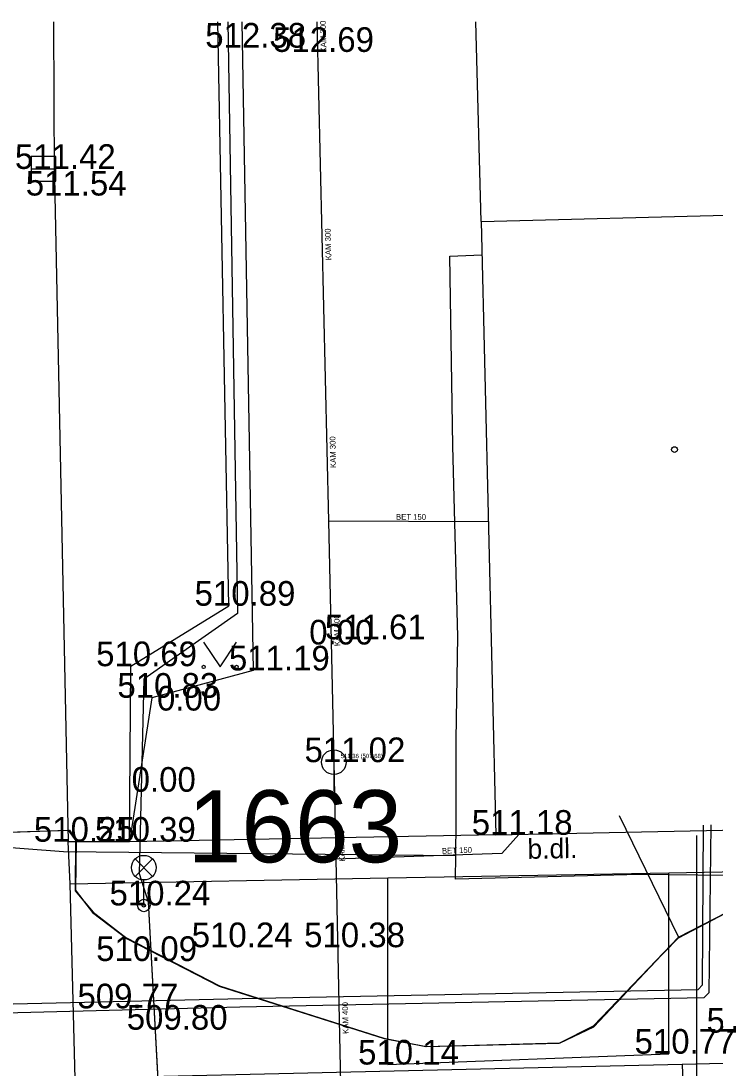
# Model space of a CAD drawing. Extents: x -669642 to -669119, y -1131006 to -1130466.
# Drawn here: x -669468.22 to -669447.11, y -1130529.04 to -1130497.18 of the extents above; entities that cross this region are included whole.
import ezdxf

# ---------------------------------------------------------------- set-up
doc = ezdxf.new("R2010")
doc.units = 0
for name, color, linetype in [('G_Bod_tecka', 7, 'Continuous'), ('G_Bod_vyska', 7, 'Continuous'), ('G_Breh_Teren', 7, 'Continuous'), ('G_Budovy-znacky', 7, 'Continuous'), ('G_Budovy_Objekty', 7, 'Continuous'), ('G_Cesty_Schody', 7, 'Continuous'), ('G_Objekty_technicke', 7, 'Continuous'), ('G_Plochy_zpevnene', 7, 'Continuous'), ('G_Popisy_povrchu', 7, 'Continuous'), ('G_Site-kanalizace', 7, 'Continuous'), ('G_Z_CHRANICKA-TEPLOVOD_kotovane', 7, 'Continuous'), ('G_Z_CHRANICKA-TEPLOVOD_zahozene', 7, 'Continuous'), ('G_Z_ELsilove_podz_kotovane', 7, 'Continuous'), ('G_Z_KANAL_podz_kotovane', 7, 'Continuous'), ('G_Z_PLYNY_podz_geodeticky', 7, 'Continuous'), ('G_Z_SPOJE_podz_geodeticky', 7, 'Continuous'), ('G_Z_SPOJE_podz_kotovane', 7, 'Continuous'), ('G_Z_SPOJE_podz_priblizne', 7, 'Continuous'), ('G_Z_SPOJE_podz_zahozene', 7, 'Continuous'), ('G_Zelen-okraj', 7, 'Continuous'), ('G_Zelen-Znacky', 7, 'Continuous'), ('Vrstva 1', 7, 'Continuous'), ('Vrstva 10', 7, 'Continuous'), ('Vrstva 11', 7, 'Continuous'), ('Vrstva 13', 7, 'Continuous'), ('Vrstva 17', 7, 'Continuous'), ('Vrstva 2', 7, 'Continuous'), ('Vrstva 3', 7, 'Continuous'), ('Vrstva 4', 7, 'Continuous'), ('Vrstva 8', 7, 'Continuous')]:
    doc.layers.add(name, color=color, linetype=linetype)

msp = doc.modelspace()

# ---------------------------------------------------------------- linework, layer by layer
at = {"layer": 'G_Bod_tecka'}
for p, q in [((-669461.59, -1130497.99), (-669461.59, -1130497.99)), ((-669459.51, -1130498.12), (-669459.51, -1130498.12)), ((-669467.53, -1130501.68), (-669467.53, -1130501.68)), ((-669467.19, -1130502.49), (-669467.19, -1130502.49)), ((-669461.89, -1130514.97), (-669461.89, -1130514.97)), ((-669458.14, -1130515.99), (-669458.14, -1130515.99)), ((-669458.67, -1130516.15), (-669458.67, -1130516.15)), ((-669464.87, -1130516.81), (-669464.87, -1130516.81)), ((-669461.15, -1130516.94), (-669461.15, -1130516.94)), ((-669464.24, -1130517.77), (-669464.24, -1130517.77)), ((-669463.3, -1130518.16), (-669463.3, -1130518.16)), ((-669458.7, -1130519.73), (-669458.7, -1130519.73)), ((-669464.07, -1130520.63), (-669464.07, -1130520.63)), ((-669453.77, -1130521.94), (-669453.77, -1130521.94)), ((-669466.78, -1130522.15), (-669466.78, -1130522.15)), ((-669464.92, -1130522.15), (-669464.92, -1130522.15)), ((-669464.48, -1130524.09), (-669464.48, -1130524.09)), ((-669461.98, -1130525.36), (-669461.98, -1130525.36)), ((-669458.56, -1130525.36), (-669458.56, -1130525.36)), ((-669464.86, -1130525.78), (-669464.86, -1130525.78)), ((-669465.31, -1130527.22), (-669465.31, -1130527.22)), ((-669463.79, -1130527.87), (-669463.79, -1130527.87)), ((-669448.51, -1130528.6), (-669448.51, -1130528.6)), ((-669457.06, -1130528.93), (-669457.06, -1130528.93))]:
    msp.add_line(p, q, dxfattribs=at)
at = {"layer": 'G_Breh_Teren'}
for p, q in [((-669461.502, -1130497.207), (-669461.15, -1130516.94)), ((-669461.15, -1130516.94), (-669464.24, -1130517.77)), ((-669464.24, -1130517.77), (-669464.92, -1130522.15))]:
    msp.add_line(p, q, dxfattribs=at)
at = {"layer": 'G_Budovy-znacky'}
msp.add_circle((-669448.34, -1130510.22), 0.0875, dxfattribs=at)
at = {"layer": 'G_Budovy_Objekty'}
for p, q in [((-669454.22, -1130503.28), (-669454.384, -1130497.207)), ((-669454.22, -1130503.28), (-669442.81, -1130502.99)), ((-669454.22, -1130503.28), (-669453.77, -1130521.94)), ((-669453.77, -1130521.94), (-669442.37, -1130521.7))]:
    msp.add_line(p, q, dxfattribs=at)
at = {"layer": 'G_Cesty_Schody'}
for p, q in [((-669467.2, -1130501.87), (-669467.215, -1130497.207)), ((-669467.2, -1130501.87), (-669467.19, -1130502.49)), ((-669467.19, -1130502.49), (-669466.78, -1130522.15))]:
    msp.add_line(p, q, dxfattribs=at)
at = {"layer": 'G_Objekty_technicke'}
for p, q in [((-669464.745, -1130522.675), (-669464.215, -1130523.205)), ((-669464.745, -1130523.205), (-669464.215, -1130522.675)), ((-669464.48, -1130524.09), (-669464.48, -1130523.315))]:
    msp.add_line(p, q, dxfattribs=at)
for centre, radius in [((-669464.48, -1130522.94), 0.375), ((-669464.48, -1130524.09), 0.19), ((-669464.48, -1130524.09), 0.05)]:
    msp.add_circle(centre, radius, dxfattribs=at)
at = {"layer": 'G_Plochy_zpevnene'}
for p, q in [((-669461.89, -1130514.97), (-669462.226, -1130497.207)), ((-669464.87, -1130516.81), (-669461.89, -1130514.97)), ((-669464.92, -1130522.15), (-669464.87, -1130516.81)), ((-669453.77, -1130521.94), (-669464.92, -1130522.15)), ((-669466.72, -1130523.43), (-669466.78, -1130522.15)), ((-669464.92, -1130522.15), (-669466.78, -1130522.15)), ((-669466.52, -1130531.1), (-669466.72, -1130523.43))]:
    msp.add_line(p, q, dxfattribs=at)
msp.add_lwpolyline([(-669466.72, -1130523.43), (-669457.06, -1130523.25), (-669448.51, -1130523.1), (-669439.35, -1130522.93)], dxfattribs=at)
at = {"layer": 'G_Site-kanalizace'}
for p, q in [((-669467.905, -1130501.68), (-669467.155, -1130501.68)), ((-669458.7, -1130519.355), (-669458.7, -1130520.605))]:
    msp.add_line(p, q, dxfattribs=at)
msp.add_lwpolyline([(-669467.905, -1130502.054), (-669467.155, -1130502.054), (-669467.155, -1130501.304), (-669467.905, -1130501.304)], close=True, dxfattribs=at)
msp.add_circle((-669458.7, -1130519.73), 0.375, dxfattribs=at)
at = {"layer": 'G_Z_CHRANICKA-TEPLOVOD_kotovane'}
for points in [[(-669447.23, -1130521.64), (-669447.29, -1130526.75), (-669447.45, -1130526.9), (-669461.56, -1130527.18), (-669481.44, -1130527.69)], [(-669481.1, -1130527.38), (-669461.49, -1130526.92), (-669447.62, -1130526.65), (-669447.49, -1130526.51), (-669447.46, -1130521.65)]]:
    msp.add_lwpolyline(points, dxfattribs=at)
at = {"layer": 'G_Z_CHRANICKA-TEPLOVOD_zahozene'}
msp.add_line((-669447.67, -1130521.96), (-669447.67, -1130535.89), dxfattribs=at)
at = {"layer": 'G_Z_ELsilove_podz_kotovane'}
msp.add_lwpolyline([(-669461.927, -1130497.207), (-669461.63, -1130515.21), (-669464.48, -1130517.2), (-669464.62, -1130523.12), (-669464.35, -1130523.98), (-669463.69, -1130536.15), (-669459.59, -1130539.64), (-669453.93, -1130539.67), (-669453.33, -1130540.17)], dxfattribs=at)
at = {"layer": 'G_Z_KANAL_podz_kotovane'}
msp.add_line((-669454, -1130512.42), (-669458.86, -1130512.4), dxfattribs=at)
for points in [[(-669459.215, -1130497.207), (-669458.86, -1130512.4), (-669458.7, -1130519.73)], [(-669458.7, -1130519.73), (-669458.64, -1130522.68), (-669458.02, -1130552.46)], [(-669453.07, -1130521.93), (-669453.59, -1130522.51), (-669458.64, -1130522.68)]]:
    msp.add_lwpolyline(points, dxfattribs=at)
at = {"layer": 'G_Z_PLYNY_podz_geodeticky'}
for points in [[(-669532.74, -1130558.83), (-669531.49, -1130552.09), (-669534.06, -1130537.73), (-669534.79, -1130531.23), (-669520.82, -1130530.69), (-669481.4, -1130529.69), (-669448.11, -1130528.92), (-669445.21, -1130528.85), (-669441.37, -1130524.47)], [(-669448.11, -1130528.92), (-669447.27, -1130552.99), (-669447.2, -1130556.63)]]:
    msp.add_lwpolyline(points, dxfattribs=at)
at = {"layer": 'G_Z_SPOJE_podz_geodeticky'}
for points in [[(-669454.99, -1130522.58), (-669454.98, -1130521.55), (-669454.98, -1130519.04), (-669454.93, -1130515.91), (-669455.03, -1130512.06), (-669455.08, -1130510.11), (-669455.17, -1130504.33), (-669454.2, -1130504.29)], [(-669454.99, -1130522.58), (-669466.92, -1130522.46), (-669471.85, -1130522.08), (-669482.12, -1130521.24), (-669486.32, -1130521.33)], [(-669434.59, -1130528.46), (-669435.08, -1130525.45), (-669439.85, -1130525.36), (-669446.76, -1130523.18), (-669449.38, -1130523.15), (-669455, -1130523.29), (-669454.99, -1130522.58)]]:
    msp.add_lwpolyline(points, dxfattribs=at)
at = {"layer": 'G_Z_SPOJE_podz_kotovane'}
for points in [[(-669472.14, -1130521.98), (-669466.74, -1130521.8), (-669466.56, -1130522.08), (-669466.57, -1130523.64), (-669466.02, -1130524.29), (-669465.03, -1130525.06), (-669462.18, -1130526.54), (-669457.19, -1130528.13), (-669455.9, -1130528.38), (-669451.82, -1130528.27), (-669450.79, -1130527.78), (-669448.22, -1130525.05), (-669445.3, -1130523.56), (-669441.55, -1130524.64), (-669439.77, -1130525.54), (-669435.75, -1130525.44), (-669435.54, -1130521.19), (-669435.54, -1130516.75), (-669435.48, -1130505.22), (-669435.71, -1130497.207)], [(-669454.99, -1130522.58), (-669454.98, -1130521.55), (-669454.98, -1130519.04), (-669454.93, -1130515.91), (-669455.03, -1130512.06), (-669455.08, -1130510.11), (-669455.17, -1130504.33), (-669454.2, -1130504.29)], [(-669454.99, -1130522.58), (-669466.92, -1130522.46), (-669471.85, -1130522.08), (-669482.12, -1130521.24), (-669486.32, -1130521.33)], [(-669434.59, -1130528.46), (-669435.08, -1130525.45), (-669439.85, -1130525.36), (-669446.76, -1130523.18), (-669449.38, -1130523.15), (-669455, -1130523.29), (-669454.99, -1130522.58)]]:
    msp.add_lwpolyline(points, dxfattribs=at)
at = {"layer": 'G_Z_SPOJE_podz_priblizne'}
for points in [[(-669454.99, -1130522.58), (-669454.98, -1130521.55), (-669454.98, -1130519.04), (-669454.93, -1130515.91), (-669455.03, -1130512.06), (-669455.08, -1130510.11), (-669455.17, -1130504.33), (-669454.2, -1130504.29)], [(-669454.99, -1130522.58), (-669466.92, -1130522.46), (-669471.85, -1130522.08), (-669482.12, -1130521.24), (-669486.32, -1130521.33)], [(-669450.02, -1130521.35), (-669448.22, -1130525.05)], [(-669434.59, -1130528.46), (-669435.08, -1130525.45), (-669439.85, -1130525.36), (-669446.76, -1130523.18), (-669449.38, -1130523.15), (-669455, -1130523.29), (-669454.99, -1130522.58)]]:
    msp.add_lwpolyline(points, dxfattribs=at)
at = {"layer": 'G_Z_SPOJE_podz_zahozene'}
for p, q in [((-669472.13, -1130521.98), (-669466.78, -1130521.8)), ((-669472.1, -1130521.98), (-669466.79, -1130521.8)), ((-669466.79, -1130521.8), (-669466.78, -1130521.8)), ((-669466.78, -1130521.8), (-669466.74, -1130521.8)), ((-669466.78, -1130521.8), (-669466.56, -1130522.1)), ((-669466.74, -1130521.8), (-669466.56, -1130522.08)), ((-669466.56, -1130522.08), (-669466.56, -1130522.1)), ((-669466.56, -1130522.1), (-669466.57, -1130523.64)), ((-669466.56, -1130522.1), (-669466.54, -1130522.12)), ((-669466.54, -1130522.12), (-669466.56, -1130523.62)), ((-669466.57, -1130523.64), (-669466.31, -1130523.95)), ((-669466.56, -1130523.62), (-669466.31, -1130523.95)), ((-669466.31, -1130523.95), (-669466.02, -1130524.29)), ((-669466.31, -1130523.95), (-669466.04, -1130524.3)), ((-669448.22, -1130525.05), (-669446.09, -1130523.96)), ((-669448.22, -1130525.07), (-669446.09, -1130523.96)), ((-669466.04, -1130524.3), (-669464.99, -1130525.11)), ((-669466.02, -1130524.29), (-669465.03, -1130525.06)), ((-669465.03, -1130525.06), (-669462.18, -1130526.54)), ((-669464.99, -1130525.11), (-669462.19, -1130526.54)), ((-669449.12, -1130526), (-669448.22, -1130525.05)), ((-669449.12, -1130526), (-669448.22, -1130525.07)), ((-669450.8, -1130527.75), (-669449.12, -1130526)), ((-669450.79, -1130527.78), (-669449.12, -1130526)), ((-669462.19, -1130526.54), (-669457.18, -1130528.13)), ((-669462.18, -1130526.54), (-669457.19, -1130528.13)), ((-669451.83, -1130528.27), (-669450.8, -1130527.75)), ((-669451.82, -1130528.27), (-669450.79, -1130527.78)), ((-669457.19, -1130528.13), (-669457.18, -1130528.13)), ((-669457.18, -1130528.13), (-669455.9, -1130528.38)), ((-669457.18, -1130528.13), (-669457.17, -1130528.14)), ((-669457.17, -1130528.14), (-669455.88, -1130528.38)), ((-669455.9, -1130528.38), (-669451.83, -1130528.27)), ((-669455.88, -1130528.38), (-669451.85, -1130528.28)), ((-669451.85, -1130528.28), (-669451.83, -1130528.27)), ((-669451.83, -1130528.27), (-669451.82, -1130528.27))]:
    msp.add_line(p, q, dxfattribs=at)
at = {"layer": 'G_Zelen-okraj'}
for p, q in [((-669457.06, -1130528.93), (-669457.06, -1130523.25)), ((-669448.51, -1130528.6), (-669448.51, -1130523.1)), ((-669457.06, -1130528.93), (-669448.51, -1130528.6))]:
    msp.add_line(p, q, dxfattribs=at)
at = {"layer": 'G_Zelen-Znacky'}
for p, q in [((-669462.66, -1130516.08), (-669462.16, -1130516.83)), ((-669462.16, -1130516.83), (-669461.66, -1130516.08))]:
    msp.add_line(p, q, dxfattribs=at)
for centre in [(-669462.66, -1130516.83), (-669461.66, -1130516.83)]:
    msp.add_circle(centre, 0.05, dxfattribs=at)
at = {"layer": 'Vrstva 1'}
msp.add_line((-669464.35, -1130523.98), (-669464.35, -1130523.98), dxfattribs=at)
at = {"layer": 'Vrstva 10'}
for points in [[(-669459.215, -1130497.207), (-669458.859, -1130512.401), (-669458.7, -1130519.73)], [(-669458.7, -1130519.73), (-669458.642, -1130522.681), (-669458.023, -1130552.455)]]:
    msp.add_lwpolyline(points, dxfattribs=at)
at = {"layer": 'Vrstva 11'}
for points in [[(-669472.14, -1130521.98), (-669466.74, -1130521.8), (-669466.56, -1130522.08), (-669466.57, -1130523.64), (-669466.02, -1130524.29), (-669465.03, -1130525.06), (-669462.18, -1130526.54), (-669457.19, -1130528.13), (-669455.9, -1130528.38), (-669451.82, -1130528.27), (-669450.79, -1130527.78), (-669448.22, -1130525.05), (-669445.3, -1130523.56), (-669441.55, -1130524.64), (-669439.77, -1130525.54), (-669435.75, -1130525.44), (-669435.54, -1130521.19), (-669435.54, -1130516.75), (-669435.48, -1130505.22), (-669435.71, -1130497.207)], [(-669472.101, -1130521.981), (-669466.785, -1130521.8), (-669466.543, -1130522.122), (-669466.563, -1130523.616), (-669466.039, -1130524.302), (-669464.99, -1130525.109), (-669462.187, -1130526.541), (-669457.172, -1130528.135), (-669455.882, -1130528.377), (-669451.848, -1130528.277), (-669450.799, -1130527.752), (-669448.218, -1130525.068), (-669445.304, -1130523.555), (-669441.533, -1130524.645), (-669439.798, -1130525.532), (-669435.745, -1130525.432), (-669435.543, -1130521.235), (-669435.543, -1130516.747), (-669435.482, -1130505.21), (-669435.689, -1130497.207)], [(-669472.101, -1130521.981), (-669466.785, -1130521.8), (-669466.543, -1130522.122), (-669466.563, -1130523.616), (-669466.039, -1130524.302), (-669464.99, -1130525.109), (-669462.187, -1130526.541), (-669457.172, -1130528.135), (-669455.882, -1130528.377), (-669451.848, -1130528.277), (-669450.799, -1130527.752), (-669448.218, -1130525.068), (-669445.304, -1130523.555), (-669441.533, -1130524.645), (-669439.798, -1130525.532), (-669435.745, -1130525.432), (-669435.543, -1130521.235), (-669435.543, -1130516.747), (-669435.482, -1130505.21), (-669435.689, -1130497.207)]]:
    msp.add_lwpolyline(points, dxfattribs=at)
at = {"layer": 'Vrstva 13'}
msp.add_line((-669454, -1130512.417), (-669458.859, -1130512.401), dxfattribs=at)
msp.add_lwpolyline([(-669453.073, -1130521.926), (-669453.593, -1130522.508), (-669458.642, -1130522.681)], dxfattribs=at)
at = {"layer": 'Vrstva 17'}
for p, q in [((-669461.927, -1130497.207), (-669461.63, -1130515.21)), ((-669461.63, -1130515.21), (-669464.48, -1130517.2)), ((-669464.48, -1130517.2), (-669464.62, -1130523.12)), ((-669464.62, -1130523.12), (-669464.35, -1130523.98)), ((-669464.35, -1130523.98), (-669463.69, -1130536.15))]:
    msp.add_line(p, q, dxfattribs=at)
at = {"layer": 'Vrstva 8'}
msp.add_line((-669458.7, -1130519.73), (-669458.7, -1130519.73), dxfattribs=at)

# ---------------------------------------------------------------- texts
at = {"layer": 'G_Bod_vyska'}
for s, p in [('512.38', (-669462.612, -1130497.99)), ('512.69', (-669460.548, -1130498.12)), ('511.42', (-669468.401, -1130501.68)), ('511.54', (-669468.071, -1130502.49)), ('510.89', (-669462.936, -1130514.97)), ('0.00', (-669459.45, -1130516.15)), ('511.61', (-669458.973, -1130515.99)), ('510.69', (-669465.93, -1130516.81)), ('511.19', (-669461.891, -1130516.94)), ('510.83', (-669465.284, -1130517.77)), ('0.00', (-669464.08, -1130518.16)), ('511.02', (-669459.592, -1130519.73)), ('0.00', (-669464.85, -1130520.63)), ('510.25', (-669467.824, -1130522.15)), ('510.39', (-669465.966, -1130522.15)), ('511.18', (-669454.506, -1130521.94)), ('510.24', (-669465.524, -1130524.09)), ('510.24', (-669463.024, -1130525.36)), ('510.38', (-669459.604, -1130525.36)), ('510.09', (-669465.928, -1130525.78)), ('509.77', (-669466.498, -1130527.22)), ('509.80', (-669464.999, -1130527.87)), ('511.08', (-669447.362, -1130527.96)), ('510.77', (-669449.554, -1130528.6)), ('510.14', (-669457.962, -1130528.93))]:
    msp.add_text(s, height=0.75, dxfattribs=at).set_placement(p)
at = {"layer": 'G_Popisy_povrchu'}
msp.add_text('b.dl.', height=0.6, rotation=1.0465, dxfattribs=at).set_placement((-669452.805, -1130522.673))
at = {"layer": 'Vrstva 2'}
msp.add_text('511.36 (507.68)', height=0.13163, dxfattribs=at).set_placement((-669458.494, -1130519.608))
at = {"layer": 'Vrstva 3'}
for s, rotation, p in [('KAM 300', 91.3188, (-669458.924, -1130498.133)), ('KAM 300', 91.3509, (-669458.777, -1130504.456)), ('KAM 300', 91.3188, (-669458.631, -1130510.779)), ('BET 150', 359.8122, (-669456.809, -1130512.355)), ('KAM 300', 91.3509, (-669458.506, -1130516.198)), ('KAM 400', 91.1908, (-669458.362, -1130522.757)), ('BET 150', 1.9467, (-669455.41, -1130522.517)), ('KAM 400', 91.158, (-669458.253, -1130527.994))]:
    msp.add_text(s, height=0.1755, rotation=rotation, dxfattribs=at).set_placement(p)
at = {"layer": 'Vrstva 4'}
msp.add_text('1663', height=2.1939, dxfattribs=at).set_placement((-669463.147, -1130522.778))

doc.saveas('drawing.dxf')
